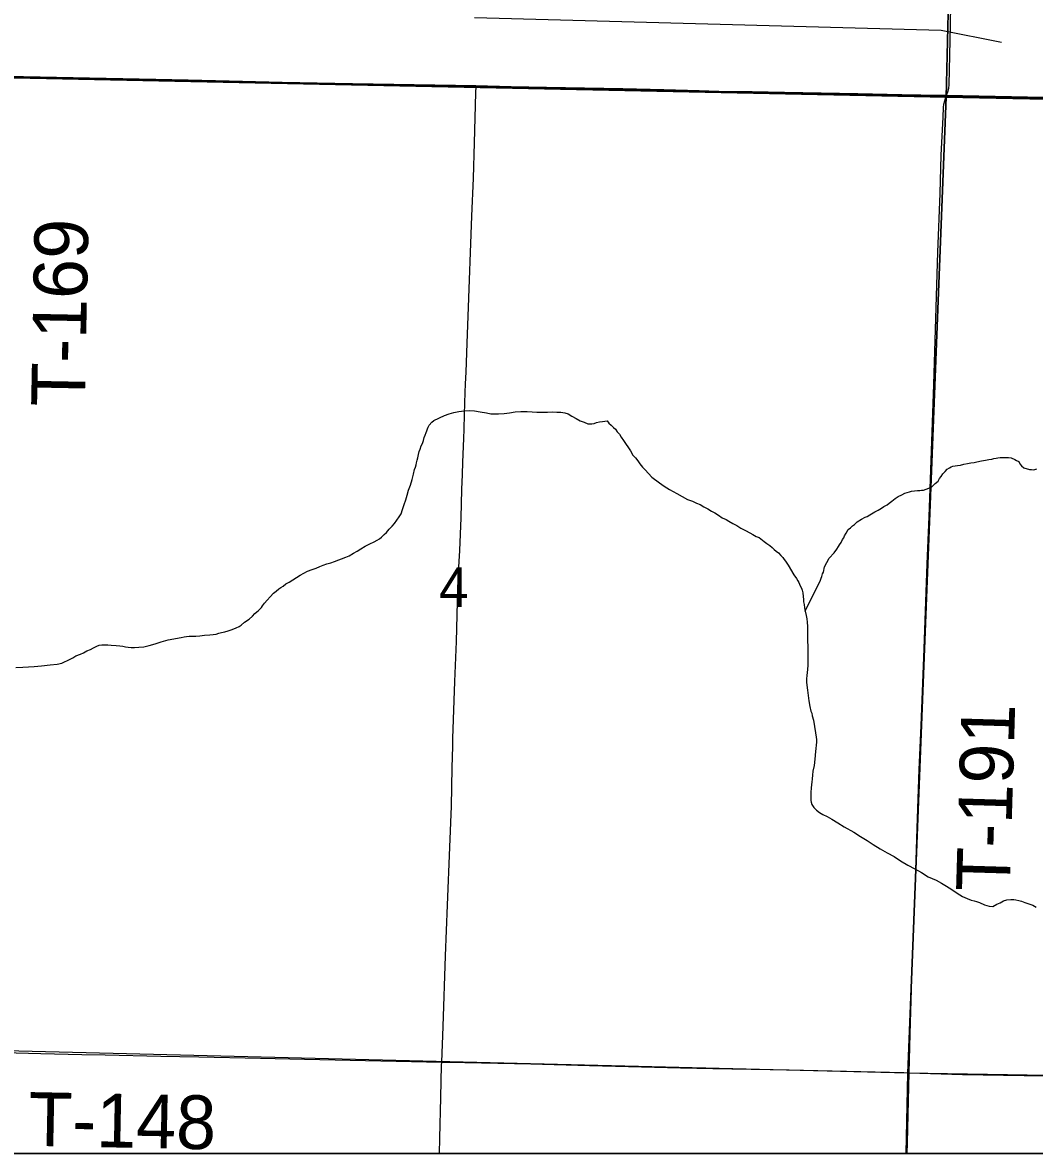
# Model space of a CAD drawing. Extents: x 2.4 to 73.1, y 4.5 to 25.6.
# Drawn here: x 34.475 to 35.01, y 17.985 to 18.583 of the extents above; entities that cross this region are included whole.
import ezdxf

# ---------------------------------------------------------------- set-up
doc = ezdxf.new("R2010")
doc.units = 0
for name, color, linetype in [('GM_X_County_Road', 7, 'Continuous'), ('GM_X_Interchange_Ramps', 7, 'Continuous'), ('GM_X_Minor_River', 7, 'Continuous'), ('GM_X_Section', 7, 'Continuous'), ('GM_X_Section_Text', 7, 'Continuous'), ('GM_X_Township_Road', 7, 'Continuous'), ('GM_X_Township_Road_Text', 7, 'Continuous'), ('GM_X_US_Shield', 7, 'Continuous'), ('SH_Cut_Line', 7, 'Continuous'), ('SH_Data', 7, 'Continuous')]:
    doc.layers.add(name, color=color, linetype=linetype)

msp = doc.modelspace()

# ---------------------------------------------------------------- linework, layer by layer
at = {"layer": 'GM_X_County_Road'}
for points in [[(34.46155, 18.55438), (34.47574, 18.5541), (34.54566, 18.55266), (34.56274, 18.5523), (34.58449, 18.55188), (34.61244, 18.55117), (34.64973, 18.5505), (34.7041, 18.54955), (34.71491, 18.54932)], [(34.71491, 18.54932), (34.73362, 18.54891), (34.75225, 18.54845), (34.79265, 18.54771), (34.8144, 18.54721), (34.83303, 18.5467), (34.84857, 18.54625), (34.861, 18.5462), (34.87808, 18.54591), (34.91692, 18.54518), (34.94022, 18.54469), (34.96042, 18.5443), (34.96362, 18.54423)], [(34.96362, 18.54423), (35.0412, 18.54265), (35.09092, 18.54186), (35.11734, 18.54162), (35.16239, 18.54072), (35.19189, 18.5399), (35.2105, 18.53881), (35.22449, 18.5383), (35.27887, 18.53736), (35.32392, 18.53649), (35.37519, 18.53541), (35.39849, 18.53482), (35.41714, 18.53456), (35.45287, 18.53389), (35.46812, 18.53354)]]:
    msp.add_lwpolyline(points, dxfattribs=at)
at = {"layer": 'GM_X_Interchange_Ramps'}
for points in [[(35.04109, 18.54292), (34.9635, 18.54451), (34.96031, 18.54458), (34.9401, 18.54497), (34.91681, 18.54545), (34.87796, 18.54618), (34.86088, 18.54647), (34.84845, 18.54653), (34.83291, 18.54698), (34.81428, 18.54749), (34.79254, 18.54798), (34.75214, 18.54873), (34.7335, 18.54919), (34.7148, 18.54959), (34.70399, 18.54983), (34.64961, 18.55077), (34.61232, 18.55145), (34.58437, 18.55216), (34.56262, 18.55258), (34.54554, 18.55294), (34.47562, 18.55437), (34.46143, 18.55465)], [(33.45306, 17.98522), (36.29738, 17.98522)]]:
    msp.add_lwpolyline(points, dxfattribs=at)
at = {"layer": 'GM_X_Minor_River'}
for points in [[(34.99283, 18.57262), (34.9609, 18.57898), (34.71412, 18.58558)], [(34.59244, 18.26603), (34.59491, 18.26774), (34.59662, 18.26925), (34.59796, 18.27058), (34.59891, 18.27153), (34.59986, 18.27229), (34.60139, 18.2738), (34.60196, 18.27475), (34.6031, 18.27608), (34.60444, 18.27778), (34.60596, 18.27949), (34.60786, 18.28139), (34.6092, 18.28252), (34.61053, 18.28366), (34.61167, 18.28442), (34.61281, 18.28517), (34.61434, 18.28631), (34.61605, 18.28725), (34.61795, 18.28839), (34.61986, 18.28972), (34.62195, 18.29085), (34.62385, 18.29199), (34.62576, 18.29312), (34.62823, 18.29387), (34.63032, 18.29463), (34.63223, 18.29557), (34.63413, 18.29614), (34.63603, 18.29689), (34.63812, 18.29746), (34.64003, 18.29821), (34.64611, 18.30047), (34.64783, 18.30123), (34.65011, 18.30255), (34.65201, 18.30369), (34.65392, 18.30482), (34.6562, 18.30634), (34.65867, 18.30747), (34.66096, 18.3086), (34.66267, 18.30936), (34.66381, 18.31012), (34.66496, 18.31106), (34.66629, 18.31239), (34.66762, 18.31353), (34.66896, 18.31523), (34.67048, 18.31675), (34.67181, 18.31827), (34.67296, 18.31997), (34.67429, 18.32168), (34.67524, 18.32339), (34.67601, 18.32567), (34.67696, 18.32833), (34.67773, 18.33079), (34.67849, 18.33326), (34.67926, 18.33592), (34.68021, 18.33858), (34.68117, 18.34143), (34.68175, 18.34428), (34.68232, 18.34675), (34.68289, 18.34808), (34.68328, 18.34922), (34.68347, 18.35036), (34.68385, 18.35169), (34.68404, 18.35302), (34.68443, 18.35473), (34.68481, 18.35624), (34.68538, 18.35757), (34.68596, 18.35928), (34.68653, 18.36061), (34.6871, 18.36213), (34.68748, 18.36365), (34.68806, 18.36498), (34.68844, 18.36631), (34.68882, 18.36726), (34.6892, 18.36821), (34.68958, 18.36916), (34.69016, 18.3703), (34.69149, 18.37181), (34.69263, 18.37276), (34.69815, 18.3754), (34.70062, 18.37616), (34.7031, 18.37691), (34.70576, 18.37747), (34.70861, 18.37785), (34.71128, 18.37803), (34.71413, 18.37783), (34.71717, 18.37725), (34.7204, 18.37667), (34.72268, 18.37629), (34.72458, 18.37628), (34.72686, 18.37627), (34.72972, 18.37645), (34.73257, 18.37683), (34.73561, 18.3772), (34.73865, 18.37738), (34.74189, 18.37737), (34.74455, 18.37736), (34.74702, 18.37716), (34.75006, 18.37716), (34.75272, 18.37715), (34.75519, 18.37733), (34.75767, 18.37713)], [(34.75767, 18.37713), (34.75976, 18.37713), (34.76185, 18.37674), (34.76356, 18.37617), (34.76565, 18.37502), (34.76793, 18.37368), (34.77002, 18.37254), (34.77211, 18.37177), (34.77401, 18.37101), (34.7761, 18.371), (34.77743, 18.37119), (34.77857, 18.37156), (34.78028, 18.37194), (34.7818, 18.37212), (34.78294, 18.37231), (34.78428, 18.3725), (34.78522, 18.37135), (34.78636, 18.37021), (34.78769, 18.36907), (34.78864, 18.36811), (34.78959, 18.36678), (34.79073, 18.36545), (34.79168, 18.36392), (34.79281, 18.36221), (34.79661, 18.35669), (34.79774, 18.3544), (34.79926, 18.35288), (34.8004, 18.35135), (34.80154, 18.34983), (34.80287, 18.34811), (34.80438, 18.34659), (34.80609, 18.34468), (34.8078, 18.34278), (34.81198, 18.33972), (34.81445, 18.33801), (34.81729, 18.33629), (34.82109, 18.33419), (34.82394, 18.33247), (34.82679, 18.33094), (34.82945, 18.32998), (34.83154, 18.32902), (34.83344, 18.32826), (34.83534, 18.32711), (34.83743, 18.32597), (34.83952, 18.32482), (34.84123, 18.32386), (34.84313, 18.32272), (34.84503, 18.32119), (34.84712, 18.32043), (34.84864, 18.31947), (34.85073, 18.31832), (34.85282, 18.31718), (34.8549, 18.31584), (34.85737, 18.3145), (34.85965, 18.31336), (34.86136, 18.3124), (34.86307, 18.31145), (34.86459, 18.31087), (34.86554, 18.31011), (34.86725, 18.30877), (34.86877, 18.30763), (34.87029, 18.30667), (34.87143, 18.30553), (34.87257, 18.30458), (34.87371, 18.30362), (34.87485, 18.30267), (34.87617, 18.30134), (34.87712, 18.30019), (34.87788, 18.29924), (34.87864, 18.29829), (34.87997, 18.29619), (34.883, 18.29105), (34.88433, 18.28915), (34.88509, 18.288), (34.88566, 18.28705), (34.88641, 18.28534), (34.88698, 18.28401), (34.88736, 18.28306), (34.88774, 18.28153), (34.88792, 18.27963), (34.88811, 18.27811), (34.88811, 18.27678), (34.88849, 18.27545), (34.88867, 18.27374), (34.88905, 18.27184), (34.88943, 18.26956), (34.8898, 18.26784), (34.88999, 18.26613), (34.89018, 18.26385), (34.89017, 18.26157), (34.89017, 18.25967), (34.89017, 18.25777), (34.89016, 18.25587), (34.89035, 18.25359), (34.89035, 18.25131), (34.89034, 18.24921), (34.89034, 18.24674), (34.89033, 18.24332), (34.89014, 18.24104), (34.88995, 18.23952), (34.88994, 18.23781)], [(34.88905, 18.27184), (34.89707, 18.28835), (34.89745, 18.2893), (34.89783, 18.29025), (34.89821, 18.29158), (34.89859, 18.29253), (34.89917, 18.29538), (34.90165, 18.29993), (34.90432, 18.30278), (34.90565, 18.30467), (34.9066, 18.306), (34.90718, 18.30695), (34.90794, 18.30828), (34.9087, 18.3098), (34.90946, 18.31074), (34.90985, 18.31169), (34.91061, 18.31321), (34.91175, 18.31511), (34.9129, 18.31587), (34.91404, 18.317), (34.91499, 18.31776), (34.91651, 18.31909), (34.9188, 18.3206), (34.9207, 18.32155), (34.92184, 18.32192), (34.92317, 18.32287), (34.92413, 18.32344), (34.92584, 18.32438), (34.92755, 18.32533), (34.92926, 18.32627), (34.9306, 18.32722), (34.93231, 18.32817), (34.93345, 18.32892), (34.93479, 18.33006), (34.9365, 18.33139), (34.93821, 18.33252), (34.94012, 18.33347), (34.94164, 18.33422), (34.94297, 18.3346), (34.94411, 18.33498), (34.94525, 18.33535), (34.94677, 18.33554), (34.9483, 18.33572), (34.94963, 18.33572), (34.95058, 18.33591), (34.95153, 18.3359), (34.95438, 18.33685), (34.9559, 18.3376), (34.95781, 18.33931), (34.95933, 18.34063), (34.96009, 18.34196), (34.96086, 18.3431), (34.96181, 18.34443), (34.96295, 18.34576), (34.9641, 18.34689), (34.96524, 18.34765), (34.96619, 18.34822), (34.96714, 18.3486), (34.96828, 18.34878), (34.96961, 18.34897), (34.97113, 18.34915), (34.97285, 18.34953), (34.97475, 18.3499), (34.97665, 18.35028), (34.97836, 18.35046), (34.97969, 18.35084), (34.98217, 18.3514), (34.98426, 18.35178), (34.98616, 18.35215), (34.98768, 18.35234), (34.98882, 18.35252), (34.98996, 18.35271), (34.99092, 18.3529), (34.99206, 18.35309), (34.99301, 18.35308), (34.99491, 18.35308), (34.99643, 18.35307), (34.99795, 18.35288), (34.99985, 18.35211), (35.0008, 18.35154), (35.00194, 18.35097), (35.00251, 18.34982), (35.00346, 18.34868), (35.0046, 18.34773), (35.00764, 18.34677), (35.00859, 18.34677), (35.00992, 18.34657), (35.01144, 18.34714)], [(34.47147, 18.24206), (34.47528, 18.24224), (34.47813, 18.24242), (34.48117, 18.2426), (34.48516, 18.24297), (34.48973, 18.24352), (34.49334, 18.24389), (34.49581, 18.24445), (34.49733, 18.24502), (34.49886, 18.24578), (34.50019, 18.24653), (34.50171, 18.24729), (34.50323, 18.24824), (34.50571, 18.24918), (34.50723, 18.24993), (34.50913, 18.25088), (34.51104, 18.25163), (34.51256, 18.25258), (34.51427, 18.25334), (34.5156, 18.2539), (34.51693, 18.25409), (34.51846, 18.25408), (34.52017, 18.25408), (34.52188, 18.25388), (34.52454, 18.25369), (34.52644, 18.25349), (34.52815, 18.2533), (34.52948, 18.2531), (34.531, 18.25291), (34.53252, 18.25271), (34.53423, 18.25271), (34.53652, 18.25289), (34.53918, 18.25307), (34.54203, 18.25382), (34.54526, 18.25458), (34.54831, 18.25571), (34.55211, 18.25665), (34.55896, 18.25796), (34.56048, 18.25833), (34.56181, 18.25852), (34.56314, 18.25871), (34.56466, 18.2587), (34.56676, 18.2587), (34.56885, 18.25888), (34.57132, 18.25925), (34.57417, 18.25943), (34.57588, 18.25962), (34.57741, 18.25981), (34.57893, 18.26018), (34.58026, 18.26056), (34.58197, 18.26093), (34.58387, 18.2615), (34.58596, 18.26225), (34.58806, 18.263), (34.58958, 18.26376), (34.59072, 18.26452), (34.59244, 18.26603)], [(34.88994, 18.23781), (34.88975, 18.2361), (34.88975, 18.23439), (34.88993, 18.23268), (34.89012, 18.23021), (34.8905, 18.22736), (34.89087, 18.2245), (34.89143, 18.22146), (34.892, 18.21899), (34.89257, 18.21804), (34.89276, 18.21651), (34.89332, 18.21423), (34.89389, 18.211), (34.89445, 18.20757), (34.89483, 18.20529), (34.89502, 18.20396), (34.89501, 18.20263), (34.89444, 18.19769), (34.89405, 18.1937), (34.89366, 18.19028), (34.89309, 18.18724), (34.89289, 18.18515), (34.8927, 18.18325), (34.89251, 18.18154), (34.89231, 18.18021), (34.89212, 18.17831), (34.89193, 18.17622), (34.89192, 18.17451), (34.89192, 18.17337), (34.89192, 18.17185), (34.89211, 18.1709), (34.89249, 18.16976), (34.89362, 18.16804), (34.89495, 18.16671), (34.89647, 18.16537), (34.89837, 18.16442), (34.90065, 18.16327), (34.90312, 18.16193), (34.90616, 18.16002), (34.90958, 18.15792), (34.91471, 18.15506), (34.91831, 18.15277), (34.92173, 18.15066), (34.92496, 18.14856), (34.92857, 18.14627), (34.93237, 18.14417), (34.93598, 18.14226), (34.9394, 18.13997), (34.9432, 18.13768), (34.94699, 18.13558), (34.95041, 18.13367), (34.95402, 18.13138), (34.9582, 18.12965), (34.96105, 18.12812), (34.96371, 18.12641), (34.96656, 18.12469), (34.96941, 18.12278), (34.97226, 18.12106), (34.97473, 18.11991), (34.97682, 18.11915), (34.97834, 18.11876), (34.97967, 18.11838), (34.98119, 18.1178), (34.98385, 18.11666), (34.98632, 18.11589), (34.98822, 18.11569), (34.99031, 18.11702), (34.99203, 18.11777), (34.99393, 18.11872), (34.99564, 18.11928), (34.99773, 18.11947), (34.99925, 18.11946), (35.00039, 18.11927), (35.00191, 18.11888), (35.00343, 18.1185), (35.00514, 18.11792), (35.00723, 18.11716), (35.00932, 18.11639), (35.01122, 18.11544)]]:
    msp.add_lwpolyline(points, dxfattribs=at)
at = {"layer": 'GM_X_Section'}
for points in [[(34.97547, 19.0472), (34.9635, 18.54362), (34.46198, 18.55402), (34.4709, 19.05673)], [(35.4772, 19.03773), (35.4673, 18.53354), (34.9635, 18.54362), (34.97547, 19.0472)], [(34.9635, 18.54362), (34.94331, 18.02771), (34.4443, 18.03995), (34.46198, 18.55402)], [(34.9635, 18.54362), (35.4673, 18.53354), (35.44866, 18.01912), (34.94331, 18.02771)]]:
    msp.add_lwpolyline(points, close=True, dxfattribs=at)
at = {"layer": 'GM_X_Township_Road'}
for points in [[(34.96362, 18.54423), (34.9645, 18.54645), (34.96501, 18.54845), (34.9651, 18.55019), (34.96581, 18.58152), (34.96617, 18.60483), (34.96655, 18.6328), (34.96721, 18.66388), (34.96769, 18.68719), (34.96805, 18.71206), (34.9696, 18.77732), (34.96983, 18.79572)], [(34.70255, 18.2006), (34.70264, 18.20461), (34.70374, 18.23475), (34.70452, 18.2559), (34.70534, 18.28392), (34.70565, 18.29238), (34.70627, 18.30401), (34.70701, 18.32118), (34.70744, 18.33617), (34.70767, 18.34409), (34.70791, 18.35068), (34.7084, 18.36311), (34.70854, 18.3681), (34.70876, 18.37579), (34.70894, 18.38195), (34.7091, 18.38747), (34.70932, 18.39208), (34.70961, 18.39832), (34.7102, 18.41361), (34.71075, 18.42785), (34.71273, 18.4807), (34.7136, 18.50089), (34.71412, 18.51955), (34.71483, 18.54598), (34.71491, 18.54932)], [(34.94401, 18.02788), (34.9445, 18.04839), (34.94542, 18.07792), (34.94666, 18.10899), (34.94737, 18.13074), (34.94776, 18.14006), (34.94824, 18.15714), (34.94934, 18.18821), (34.95024, 18.21152), (34.95186, 18.25191), (34.95345, 18.29696), (34.95455, 18.3218), (34.95551, 18.34665), (34.95706, 18.39171), (34.95774, 18.41502), (34.95921, 18.46163), (34.9603, 18.4927), (34.96098, 18.5129), (34.9619, 18.53309), (34.96218, 18.53811), (34.96235, 18.5399), (34.96276, 18.54175), (34.96327, 18.54313), (34.96362, 18.54423)], [(34.69674, 18.03346), (34.69746, 18.05227), (34.69872, 18.08958), (34.69985, 18.11638), (34.70113, 18.14708), (34.70195, 18.16884), (34.70229, 18.18906), (34.70255, 18.2006)], [(34.44538, 18.03906), (34.48468, 18.03799), (34.5064, 18.03754), (34.51882, 18.03739), (34.54814, 18.03667), (34.56832, 18.03624), (34.60094, 18.03553), (34.62424, 18.03504), (34.66462, 18.03414), (34.69674, 18.03346)], [(34.69562, 17.98522), (34.69578, 17.9932), (34.69622, 18.01483), (34.69669, 18.03192), (34.69674, 18.03346)], [(34.69674, 18.03346), (34.70034, 18.03338), (34.74383, 18.03251), (34.77489, 18.03167), (34.82303, 18.0304), (34.84012, 18.03003), (34.88051, 18.02939), (34.94108, 18.02797), (34.94401, 18.02788)], [(34.94297, 17.98522), (34.94312, 17.99089), (34.94401, 18.02788)], [(34.94401, 18.02788), (34.97213, 18.02699), (35.00475, 18.02638), (35.04669, 18.02572), (35.08862, 18.02482), (35.1026, 18.02449), (35.1228, 18.02427), (35.15386, 18.02366), (35.1725, 18.02317), (35.19424, 18.02268), (35.21598, 18.02194), (35.29675, 18.02096), (35.37753, 18.01985), (35.42568, 18.0191), (35.44432, 18.01878), (35.44932, 18.0186)]]:
    msp.add_lwpolyline(points, dxfattribs=at)
at = {"layer": 'GM_X_US_Shield'}
for points in [[(34.44309, 17.98522), (34.94245, 17.98522), (34.94331, 18.02771), (34.4443, 18.03995)], [(34.94245, 17.98522), (35.44775, 17.98522), (35.44866, 18.01912), (34.94331, 18.02771)]]:
    msp.add_lwpolyline(points, close=True, dxfattribs=at)
at = {"layer": 'SH_Cut_Line'}
msp.add_lwpolyline([(29.49738, 21.67933), (29.49738, 17.98522), (36.29738, 17.98522), (36.29738, 20.02567)], dxfattribs=at)
at = {"layer": 'SH_Data'}
msp.add_lwpolyline([(29.49738, 24.78522), (36.29738, 24.78522), (36.29738, 17.98522), (29.49738, 17.98522)], close=True, dxfattribs=at)

# ---------------------------------------------------------------- texts
at = {"layer": 'GM_X_Section_Text'}
msp.add_text('4', height=0.02093, rotation=0.00001, dxfattribs=at).set_placement((34.69534, 18.27414))
at = {"layer": 'GM_X_Township_Road_Text'}
for s, rotation, p in [('T-169', 88.87694, (34.50798, 18.37979)), ('T-191', 88.32122, (34.99715, 18.12332)), ('T-148', 358.88093, (34.47794, 17.98924))]:
    msp.add_text(s, height=0.028409, rotation=rotation, dxfattribs=at).set_placement(p)

doc.saveas('drawing.dxf')
